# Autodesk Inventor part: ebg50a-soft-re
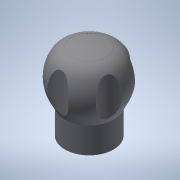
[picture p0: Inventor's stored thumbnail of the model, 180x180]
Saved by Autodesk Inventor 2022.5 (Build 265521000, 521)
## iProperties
Created: 2016-12
Part Number: ebg50a-soft-re
Material: 一般
Document SubType Name: Modeling
Designer: imaocorp
Density: 1 g/cm^3
Appearance: 既定
Author: imaocorp
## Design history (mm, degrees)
node "ebg50a-soft-re.x_t1"
node "ebg50a-soft-re"
node "Base1"
